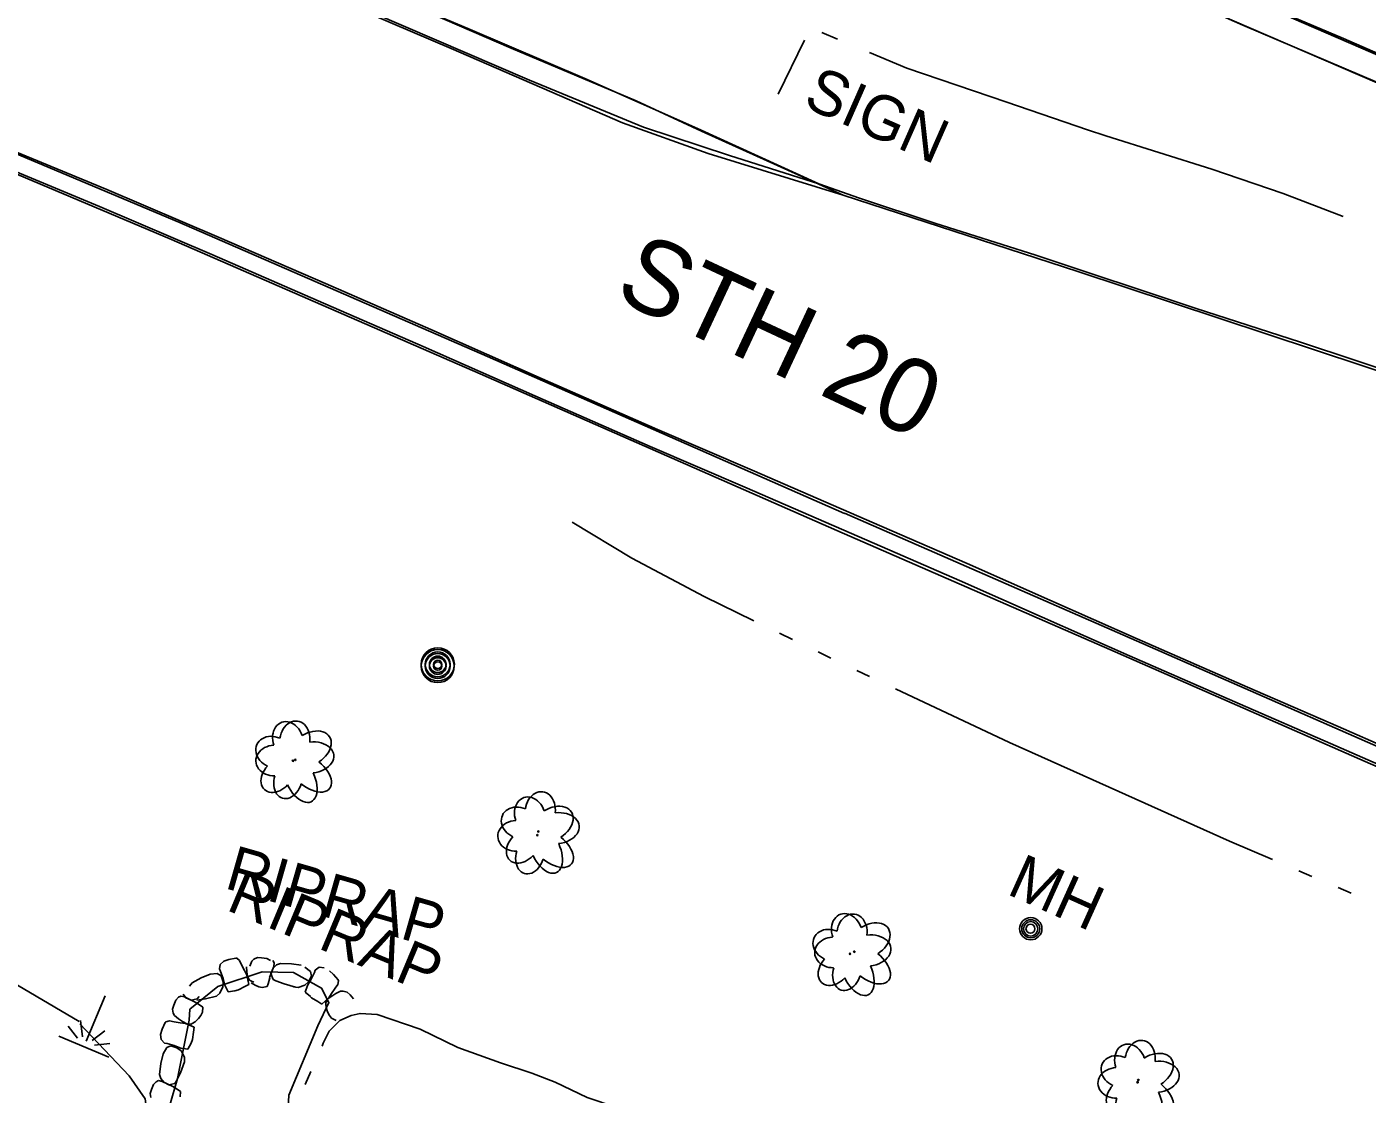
# Model space of a CAD drawing. Extents: x 588843 to 2552415, y 180129 to 269402.
# Drawn here: x 594432.4 to 594612.7, y 185134.3 to 185277.8 of the extents above; entities that cross this region are included whole.
import ezdxf

# ---------------------------------------------------------------- set-up
doc = ezdxf.new("R2010")
doc.units = 0
for name, color, linetype in [('Default', 7, 'Continuous'), ('E_DRN_RipRap', 7, 'Continuous'), ('E_DRN_RipRap_Text', 7, 'Continuous'), ('E_LAND_Vegetation', 7, 'Continuous'), ('E_MISCPROP', 7, 'Continuous'), ('E_RDWY', 7, 'Continuous'), ('E_RDWY_C_and_G', 7, 'Continuous'), ('E_RDWY_Gravel', 7, 'Continuous'), ('E_RDWY_Text', 7, 'Continuous'), ('E_SGN', 7, 'Continuous'), ('E_SGN_Text', 7, 'Continuous'), ('E_UTL_MH', 7, 'Continuous'), ('E_UTL_MH_Text', 7, 'Continuous'), ('E_WTR_P', 7, 'Continuous'), ('E_WTR_Wetland', 7, 'Continuous')]:
    doc.layers.add(name, color=color, linetype=linetype)

# ---------------------------------------------------------------- blocks, each defined once
blk = doc.blocks.new('RIPRT')
at = {"layer": 'E_DRN_RipRap_Text'}
blk.add_text('RIPRAP', height=12, dxfattribs=at).set_placement((-0.14, -3.59))
blk = doc.blocks.new('DTRE')
at = {"layer": 'Default'}
blk.add_circle((-0.18, 0), 0.183, dxfattribs=at)
for centre, major_axis, ratio in [((-1.87, 5.32), (1.36, -4.98), 0.782863), ((4.06, 2.74), (-5.27, -2.93), 0.691916), ((-5.87, 0.15), (4.93, -0.12), 0.832022), ((3.54, -3.71), (-5.01, 4.58), 0.560249), ((-2.49, -5.24), (1.8, 4.86), 0.716896)]:
    blk.add_ellipse(centre, major_axis=major_axis, ratio=ratio, start_param=1.570796, end_param=4.712389, dxfattribs=at)
blk = doc.blocks.new('MAR')
at = {"layer": 'Default'}
for p, q in [((-0.02, 14.83), (-0.02, 1.62)), ((-1.37, 2.38), (-3.54, 6.17)), ((1.39, 2.38), (3.55, 6.17)), ((-7.33, 0), (7.23, 0)), ((-6.08, 3.52), (-2.46, 1.46)), ((6.1, 3.52), (2.47, 1.46))]:
    blk.add_line(p, q, dxfattribs=at)
blk = doc.blocks.new('MHO')
at = {"layer": 'Default'}
for centre, radius in [((0.08, -0.12), 3), ((0.08, -0.12), 2.43), ((0.07, -0.15), 1.94), ((0.02, -0.16), 1.21)]:
    blk.add_circle(centre, radius, dxfattribs=at)
blk = doc.blocks.new('MHT')
at = {"layer": 'E_UTL_MH_Text'}
blk.add_text('MH', height=12, dxfattribs=at).set_placement((-9.81, -6))
blk = doc.blocks.new('POLE')
at = {"layer": 'Default'}
for radius in [4.46, 3.35, 2.23, 1.12]:
    blk.add_circle((0, 0), radius, dxfattribs=at)
blk = doc.blocks.new('SIGN')
at = {"layer": 'Default'}
blk.add_text('SIGN', height=12, dxfattribs=at).set_placement((-18.55, -6))
blk = doc.blocks.new('POLE_3')
at = {"layer": 'E_MISCPROP'}
for radius in [14.6, 11, 7.32, 3.66]:
    blk.add_circle((0, 0), radius, dxfattribs=at)
blk = doc.blocks.new('DTRE_4')
at = {"layer": 'E_LAND_Vegetation'}
blk.add_circle((-0.6, 0), 0.601, dxfattribs=at)
for centre, major_axis, ratio in [((-6.1, 17.5), (4.5, -16.3), 0.782863), ((13.3, 9), (-17.3, -9.6), 0.691916), ((-19.3, 0.5), (16.2, -0.4), 0.832022), ((11.6, -12.2), (-16.4, 15), 0.560249), ((-8.2, -17.2), (5.9, 15.9), 0.716896)]:
    blk.add_ellipse(centre, major_axis=major_axis, ratio=ratio, start_param=1.570796, end_param=4.712389, dxfattribs=at)
blk = doc.blocks.new('RIPRT_3')
at = {"layer": 'E_DRN_RipRap_Text'}
blk.add_text('RIPRAP', height=39.37, dxfattribs=at).set_placement((-0.5, -11.8))

msp = doc.modelspace()

# ---------------------------------------------------------------- linework, layer by layer
at = {"layer": 'E_DRN_RipRap'}
for p, q in [((594458.93, 185152.19), (594458.42, 185151.75)), ((594459.62, 185152.42), (594458.93, 185152.19)), ((594460.53, 185152.59), (594459.62, 185152.42)), ((594460.68, 185152.56), (594460.53, 185152.59)), ((594461.04, 185152.25), (594460.68, 185152.56)), ((594461.31, 185151.69), (594461.04, 185152.25)), ((594462.43, 185151.52), (594462.69, 185152.17)), ((594462.69, 185152.17), (594462.97, 185152.43)), ((594462.97, 185152.43), (594463.46, 185152.65)), ((594463.46, 185152.65), (594464, 185152.62)), ((594464, 185152.62), (594464.73, 185152.52)), ((594464.73, 185152.52), (594465.19, 185152.28)), ((594465.53, 185152.25), (594465.69, 185151.96)), ((594455.9, 185149.94), (594457.1, 185150.42)), ((594457.1, 185150.42), (594458.03, 185150.52)), ((594458.03, 185150.52), (594458.56, 185150.21)), ((594458.42, 185151.75), (594458.34, 185151.13)), ((594458.34, 185151.13), (594458.49, 185150.8)), ((594458.49, 185150.8), (594458.83, 185149.86)), ((594458.56, 185150.21), (594458.82, 185149.39)), ((594461.7, 185150.91), (594461.31, 185151.69)), ((594462.02, 185150.3), (594461.7, 185150.91)), ((594462, 185150.76), (594461.99, 185151.41)), ((594462.09, 185150.1), (594462, 185150.76)), ((594462.3, 185149.06), (594462.02, 185150.3)), ((594465.64, 185151.46), (594465.07, 185149.96)), ((594465.55, 185151.24), (594465.27, 185150.51)), ((594465.54, 185149.7), (594465.27, 185150.51)), ((594465.99, 185151.67), (594465.55, 185151.24)), ((594465.69, 185151.96), (594465.64, 185151.46)), ((594466.53, 185151.87), (594465.99, 185151.67)), ((594466.53, 185151.87), (594468.01, 185151.84)), ((594468.01, 185151.84), (594469.33, 185151.65)), ((594469.8, 185151.37), (594470.56, 185150.77)), ((594470.56, 185150.77), (594470.72, 185150.18)), ((594471.1, 185150.64), (594470.67, 185149.74)), ((594471.23, 185150.98), (594471.1, 185150.64)), ((594471.74, 185151.35), (594471.23, 185150.98)), ((594472.43, 185151.3), (594471.74, 185151.35)), ((594473.69, 185150.39), (594473.13, 185150.89)), ((594474.3, 185149.67), (594473.69, 185150.39)), ((594454.65, 185149.26), (594454.31, 185148.82)), ((594454.65, 185149.26), (594455.9, 185149.94)), ((594458.81, 185148.71), (594458.41, 185147.86)), ((594458.82, 185149.39), (594458.81, 185148.71)), ((594458.83, 185149.86), (594459.08, 185148.93)), ((594459.08, 185148.93), (594459.49, 185148.07)), ((594460.92, 185148.3), (594461.74, 185148.77)), ((594461.74, 185148.77), (594462.3, 185149.06)), ((594462.38, 185149.63), (594462.09, 185150.1)), ((594462.55, 185149.55), (594462.38, 185149.63)), ((594462.97, 185149.37), (594462.55, 185149.55)), ((594463.14, 185148.93), (594462.62, 185149.27)), ((594463.63, 185148.72), (594463.14, 185148.93)), ((594464.1, 185148.62), (594463.63, 185148.72)), ((594464.77, 185148.77), (594464.1, 185148.62)), ((594464.9, 185149.14), (594464.77, 185148.77)), ((594465.13, 185149.95), (594464.9, 185149.14)), ((594465.9, 185149.51), (594465.54, 185149.7)), ((594467.03, 185149.11), (594465.9, 185149.51)), ((594468.55, 185148.7), (594467.03, 185149.11)), ((594468.91, 185148.64), (594468.29, 185148.72)), ((594469.82, 185148.95), (594468.91, 185148.64)), ((594470.32, 185149.41), (594469.82, 185148.95)), ((594470.18, 185148.9), (594469.86, 185148.01)), ((594470.67, 185149.74), (594470.18, 185148.9)), ((594470.72, 185150.18), (594470.32, 185149.41)), ((594473.41, 185147.82), (594473.9, 185148.54)), ((594473.9, 185148.54), (594474.26, 185149.05)), ((594474.26, 185149.05), (594474.35, 185149.53)), ((594474.35, 185149.53), (594474.3, 185149.67)), ((594452.2, 185146.25), (594452.49, 185146.93)), ((594452.49, 185146.93), (594452.84, 185147.33)), ((594452.84, 185147.33), (594453.14, 185147.47)), ((594453.14, 185147.47), (594453.63, 185147.36)), ((594453.46, 185147.74), (594453.84, 185147.26)), ((594453.63, 185147.36), (594455.06, 185146.66)), ((594453.84, 185147.26), (594454.53, 185146.91)), ((594455.36, 185147.09), (594454.53, 185146.91)), ((594455.06, 185146.66), (594455.78, 185146.22)), ((594456.46, 185147.11), (594455.32, 185146.91)), ((594455.59, 185147.44), (594455.36, 185147.09)), ((594457.93, 185147.49), (594456.46, 185147.11)), ((594458.41, 185147.86), (594457.93, 185147.49)), ((594459.49, 185148.07), (594460.4, 185148.19)), ((594460.4, 185148.19), (594460.92, 185148.3)), ((594469.86, 185148.01), (594470.6, 185147.44)), ((594470.36, 185147.65), (594470.72, 185147.24)), ((594470.72, 185147.24), (594471.55, 185146.75)), ((594471.55, 185146.75), (594472.1, 185146.39)), ((594472.1, 185146.39), (594473.03, 185147.25)), ((594472.63, 185146.6), (594472.9, 185147.09)), ((594472.64, 185146.41), (594472.63, 185146.6)), ((594472.9, 185147.09), (594473.44, 185147.49)), ((594473.03, 185147.25), (594473.41, 185147.82)), ((594473.44, 185147.49), (594473.99, 185147.81)), ((594473.99, 185147.81), (594474.61, 185148.14)), ((594474.61, 185148.14), (594474.99, 185148.16)), ((594474.99, 185148.16), (594475.5, 185148.01)), ((594475.5, 185148.01), (594475.9, 185147.64)), ((594475.9, 185147.64), (594476.38, 185147.1)), ((594452.04, 185145.73), (594452.2, 185146.25)), ((594452.11, 185145.2), (594452.04, 185145.73)), ((594452.29, 185144.85), (594452.11, 185145.2)), ((594452.85, 185144.43), (594452.29, 185144.85)), ((594455.85, 185144.88), (594455.53, 185144.45)), ((594455.78, 185146.22), (594456.1, 185146)), ((594456.08, 185145.31), (594455.85, 185144.88)), ((594456.1, 185146), (594456.08, 185145.31)), ((594472.7, 185145.95), (594472.64, 185146.41)), ((594472.88, 185145.36), (594472.7, 185145.95)), ((594473.12, 185144.89), (594472.88, 185145.36)), ((594473.41, 185144.51), (594473.12, 185144.89)), ((594450.65, 185143.04), (594450.43, 185142.31)), ((594451.04, 185143.91), (594450.65, 185143.04)), ((594451.15, 185144.02), (594451.04, 185143.91)), ((594451.61, 185144.14), (594451.15, 185144.02)), ((594452.23, 185144.03), (594451.61, 185144.14)), ((594453.08, 185143.88), (594452.23, 185144.03)), ((594453.37, 185144.05), (594452.85, 185144.43)), ((594453.76, 185143.78), (594453.08, 185143.88)), ((594453.96, 185143.73), (594453.37, 185144.05)), ((594454.92, 185143.29), (594453.76, 185143.78)), ((594454.52, 185143.69), (594453.96, 185143.73)), ((594454.68, 185143.78), (594454.52, 185143.69)), ((594455.07, 185144.03), (594454.68, 185143.78)), ((594454.83, 185142.63), (594454.92, 185143.29)), ((594455.53, 185144.45), (594455.07, 185144.03)), ((594474.02, 185144.2), (594473.41, 185144.51)), ((594450.43, 185142.31), (594450.49, 185141.62)), ((594450.49, 185141.62), (594450.94, 185141.17)), ((594454.52, 185141.15), (594454.73, 185141.66)), ((594454.73, 185141.66), (594454.83, 185142.63)), ((594450.48, 185138.4), (594450.79, 185139.7)), ((594450.79, 185139.7), (594451.26, 185140.55)), ((594450.94, 185141.17), (594451.3, 185141.1)), ((594451.26, 185140.55), (594451.81, 185140.81)), ((594451.3, 185141.1), (594452.25, 185140.83)), ((594451.81, 185140.81), (594452.63, 185140.54)), ((594452.25, 185140.83), (594453.15, 185140.48)), ((594452.63, 185140.54), (594453.17, 185140.12)), ((594453.15, 185140.48), (594454.08, 185140.32)), ((594453.17, 185140.12), (594453.62, 185139.27)), ((594454.08, 185140.32), (594454.52, 185141.15)), ((594450.3, 185136.93), (594450.48, 185138.4)), ((594453.64, 185138.64), (594453.09, 185137.17)), ((594453.62, 185139.27), (594453.64, 185138.64)), ((594449.48, 185135.58), (594449.83, 185135.97)), ((594449.83, 185135.97), (594450.14, 185136.11)), ((594450.14, 185136.11), (594450.62, 185136.01)), ((594450.3, 185136.93), (594450.45, 185136.38)), ((594450.45, 185136.38), (594450.84, 185135.9)), ((594450.62, 185136.01), (594452.05, 185135.3)), ((594450.84, 185135.9), (594451.53, 185135.55)), ((594452.58, 185136.08), (594452.36, 185135.74)), ((594453.09, 185137.17), (594452.58, 185136.08)), ((594449.03, 185134.37), (594449.2, 185134.9)), ((594449.11, 185133.84), (594449.03, 185134.37)), ((594449.2, 185134.9), (594449.48, 185135.58)), ((594452.36, 185135.74), (594451.53, 185135.55)), ((594452.05, 185135.3), (594452.78, 185134.87)), ((594452.78, 185134.87), (594453.1, 185134.65)), ((594453.1, 185134.65), (594453.07, 185133.95))]:
    msp.add_line(p, q, dxfattribs=at)
msp.add_lwpolyline([(594454.37, 185145.74), (594458.11, 185148.77), (594464.1, 185150.74), (594468.28, 185150.67), (594472.08, 185148.56), (594473.06, 185146.64), (594471.55, 185143.49), (594467.65, 185134.16), (594467.29, 185127.19), (594465.38, 185123.03), (594458.88, 185121.41), (594455.14, 185123.71), (594452.87, 185126.51), (594450.95, 185127.67), (594449.93, 185129.5), (594451.69, 185132.79), (594452.72, 185136.38), (594454.1, 185143.36), (594454.25, 185144.24)], close=True, dxfattribs=at)
at = {"layer": 'E_RDWY'}
for points in [[(594296.88, 185411.87), (594325.62, 185399.4), (594349.95, 185388.9), (594374.77, 185378.12), (594397.2, 185368.32), (594422.63, 185357.35), (594444.66, 185347.72), (594469.29, 185337.04), (594493.12, 185326.74), (594515.85, 185316.9), (594539.82, 185306.36), (594564.27, 185295.73), (594590.16, 185284.43), (594616.48, 185273), (594638.84, 185263.28), (594667.59, 185250.7), (594695.94, 185238.13), (594716.7, 185228.91), (594730.42, 185222.27), (594740.31, 185216.94), (594750.4, 185211.08), (594752.94, 185209.36)], [(594414.5, 185307.01), (594452.18, 185290.9), (594489.48, 185274.91), (594512.53, 185264.93), (594524.05, 185260.81), (594542.22, 185255.2), (594573.77, 185244.95), (594605.57, 185234.41), (594625.49, 185227.79)], [(594784.94, 185177.8), (594785.08, 185179.2), (594784.4, 185181.48), (594783.37, 185183.2), (594781.11, 185185.75), (594772.43, 185194.02), (594762.07, 185202.45), (594754.55, 185208.28), (594750.23, 185211.44), (594745, 185214.44), (594731.64, 185221.77), (594717.43, 185228.78), (594703.51, 185235.06), (594690.51, 185240.87), (594678.43, 185246.04), (594661.35, 185253.58), (594645.43, 185260.62), (594631.02, 185266.85), (594609.49, 185276.28), (594587.28, 185285.68)], [(594618.69, 185230.45), (594603.7, 185235.43), (594589.52, 185240.02), (594568.09, 185247.12), (594554.51, 185251.44), (594544.4, 185254.81), (594538.92, 185256.74), (594526.93, 185260.54), (594515.36, 185264.33), (594500.04, 185270.65), (594478.87, 185279.78), (594470.44, 185283.43)]]:
    msp.add_lwpolyline(points, dxfattribs=at)
at = {"layer": 'E_RDWY_C_and_G'}
for points in [[(594424.81, 185263.37), (594452.87, 185251.55), (594494.39, 185233.48), (594542.37, 185212.4)], [(594423.84, 185261.06), (594451.88, 185249.25), (594493.38, 185231.18), (594541.37, 185210.11)], [(594622.66, 185177.64), (594608.75, 185183.72), (594596.58, 185189.04), (594581.71, 185195.55), (594569.97, 185200.74), (594558.86, 185205.67), (594547.4, 185210.64), (594529.95, 185218.23), (594517.25, 185223.68), (594501.75, 185230.51), (594486.74, 185237.12), (594472.59, 185243.3), (594458.3, 185249.51), (594443.2, 185255.97), (594429.76, 185261.54)], [(594716.87, 185132.54), (594713.76, 185134.58), (594711.06, 185136.08), (594699.81, 185141.15), (594684.3, 185148.01), (594670.6, 185154.04), (594659.19, 185159.04), (594643.95, 185165.72), (594631.99, 185170.86), (594621.66, 185175.35), (594607.74, 185181.43), (594595.58, 185186.75), (594580.7, 185193.26), (594568.95, 185198.46), (594557.86, 185203.38), (594546.4, 185208.35), (594528.96, 185215.94), (594516.25, 185221.38), (594500.75, 185228.22), (594485.74, 185234.83), (594471.59, 185241.01), (594457.31, 185247.21), (594442.22, 185253.67), (594428.73, 185259.27)], [(594542.37, 185212.41), (594579.07, 185196.4), (594613.4, 185181.3), (594640.21, 185169.61)], [(594541.37, 185210.11), (594578.07, 185194.11), (594612.4, 185179.01), (594639.21, 185167.32)]]:
    msp.add_lwpolyline(points, dxfattribs=at)
at = {"layer": 'E_RDWY_Gravel'}
for points in [[(594294.77, 185410.38), (594323, 185398.2), (594352.64, 185385.11), (594378.47, 185373.42), (594417.21, 185356.7), (594461.03, 185337.4), (594502.73, 185319.22), (594545.58, 185300.1), (594582.07, 185284.13), (594624.08, 185265.97), (594659.78, 185250.12), (594703.03, 185231.29), (594732.78, 185218.27), (594752.76, 185209.38), (594752.81, 185209.45)], [(594542.22, 185255.2), (594523.14, 185263.83), (594514.37, 185267.87), (594497.56, 185274.99), (594478.07, 185283.43), (594456.69, 185292.47), (594432.43, 185302.84), (594407.11, 185313.47), (594381.72, 185324.42), (594355.48, 185335.56), (594332.34, 185345.41), (594309.84, 185354.82), (594288.72, 185363.68), (594277.6, 185367.93), (594276.13, 185368.21)], [(594578.41, 185285.82), (594595.95, 185278.05), (594614.06, 185270.36), (594628.73, 185263.95), (594645.28, 185256.82), (594670.13, 185245.95), (594688.1, 185237.61), (594706.5, 185229.93), (594722.84, 185222.76), (594738.06, 185216.05), (594750.23, 185211.44)], [(594538.92, 185256.74), (594522.6, 185264.17), (594507.46, 185270.88), (594491.72, 185277.61), (594474.21, 185285.01)]]:
    msp.add_lwpolyline(points, dxfattribs=at)
at = {"layer": 'E_SGN'}
msp.add_lwpolyline([(594537.01, 185276.03), (594533.47, 185268.8)], dxfattribs=at)
at = {"layer": 'E_WTR_P'}
for points in [[(594539.31, 185277.08), (594541.45, 185276.18)], [(594545.74, 185274.38), (594550.78, 185272.26), (594564.22, 185267.7), (594575.04, 185263.99), (594577.53, 185263.2)], [(594577.53, 185263.2), (594591.75, 185258.7), (594601.36, 185255.43), (594609.42, 185252.32)], [(594530.21, 185197.96), (594523.49, 185201.23), (594513.8, 185206.36), (594505.77, 185211.22)], [(594535.38, 185195.44), (594533.66, 185196.28)], [(594540.56, 185192.92), (594538.83, 185193.76)], [(594545.76, 185190.46), (594544.03, 185191.28)], [(594574.49, 185177.14), (594564.56, 185181.59), (594549.24, 185188.82)], [(594599.92, 185165.84), (594594.14, 185168.32), (594574.49, 185177.14)], [(594605.22, 185163.58), (594603.45, 185164.33)], [(594610.51, 185161.31), (594608.75, 185162.07)], [(594439.46, 185144.07), (594430.44, 185149.41), (594422.73, 185152.3)], [(594472.14, 185140.76), (594472.3, 185141.14), (594473.07, 185142.76), (594474.51, 185144.19), (594476.04, 185144.88), (594477.24, 185145.15), (594479.55, 185145), (594485.34, 185143.04), (594490.37, 185140.57), (594496.14, 185138.51)], [(594448.43, 185120.95), (594448.75, 185121.38), (594449.69, 185123.26), (594449.52, 185125.16), (594448.29, 185127.66), (594448.71, 185130.92), (594448.37, 185133.68), (594446.18, 185136.76), (594439.59, 185143.77)], [(594496.13, 185138.52), (594500.33, 185137.11), (594503.47, 185135.9), (594507.79, 185133.85), (594511.62, 185132.55), (594517.08, 185130.88), (594520.5, 185130.31), (594521.96, 185130.03)], [(594469.87, 185135.59), (594470.63, 185137.32)]]:
    msp.add_lwpolyline(points, dxfattribs=at)

# ---------------------------------------------------------------- block references
at = {"layer": 'E_DRN_RipRap_Text'}
for name, p, xscale, yscale, rotation in [('RIPRT_3', (594459.43, 185163.75), 0.1524003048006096, 0.1524003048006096, -15.969778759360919), ('RIPRT', (594459.83, 185160.76), 0.4999999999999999, 0.49999999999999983, -22.695353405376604)]:
    msp.add_blockref(name, p, dxfattribs=dict(at, xscale=xscale, yscale=yscale, rotation=rotation))
at = {"layer": 'E_LAND_Vegetation'}
for name, p, xscale, yscale, rotation in [('DTRE', (594468.31, 185179.09), 0.4999999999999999, 0.49999999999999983, -22.695353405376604), ('DTRE_4', (594468.65, 185179.26), 0.15240030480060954, 0.15240030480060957, 3.4338469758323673), ('DTRE', (594501.31, 185169.58), 0.4999999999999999, 0.49999999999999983, -22.695353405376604), ('DTRE_4', (594501.18, 185169.13), 0.15240030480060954, 0.15240030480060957, 3.4338469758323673), ('DTRE', (594543.22, 185153.13), 0.4999999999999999, 0.49999999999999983, -22.695353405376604), ('DTRE_4', (594543.79, 185153.45), 0.15240030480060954, 0.15240030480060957, 3.4338469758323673), ('DTRE', (594581.97, 185136.14), 0.4999999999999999, 0.49999999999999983, -22.695353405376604), ('DTRE_4', (594581.87, 185135.9), 0.15240030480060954, 0.15240030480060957, 3.4338469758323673)]:
    msp.add_blockref(name, p, dxfattribs=dict(at, xscale=xscale, yscale=yscale, rotation=rotation))
at = {"layer": 'E_MISCPROP'}
for name, p, xscale, yscale, rotation in [('POLE', (594487.69, 185192.1), 0.5, 0.5, -24.25797329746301), ('POLE_3', (594487.69, 185191.86), 0.15240030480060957, 0.15240030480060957, 0.8014450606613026)]:
    msp.add_blockref(name, p, dxfattribs=dict(at, xscale=xscale, yscale=yscale, rotation=rotation))
at = {"layer": 'E_SGN_Text', "xscale": 0.5, "yscale": 0.5, "rotation": -23.807133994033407}
msp.add_blockref('SIGN', (594546.31, 185266.21), dxfattribs=at)
at = {"layer": 'E_UTL_MH', "xscale": 0.5, "yscale": 0.5, "rotation": -24.25797329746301}
msp.add_blockref('MHO', (594567.41, 185156.61), dxfattribs=at)
at = {"layer": 'E_UTL_MH_Text', "xscale": 0.5, "yscale": 0.5, "rotation": -24.25797329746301}
msp.add_blockref('MHT', (594569.73, 185162), dxfattribs=at)
at = {"layer": 'E_WTR_Wetland', "xscale": 0.4999999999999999, "yscale": 0.49999999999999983, "rotation": -22.695353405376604}
msp.add_blockref('MAR', (594440.12, 185140.66), dxfattribs=at)

# ---------------------------------------------------------------- texts
at = {"layer": 'E_RDWY_Text'}
msp.add_text('STH 20', height=10, rotation=334.929, dxfattribs=at).set_placement((594511.15, 185241.42))

doc.saveas('drawing.dxf')
